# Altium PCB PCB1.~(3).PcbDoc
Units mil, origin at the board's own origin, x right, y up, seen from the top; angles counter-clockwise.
Board outline 6000 x 4000 mil, 2 copper layers (Top Layer, Bottom Layer); 19 components, 17 nets, 64 pads, 0 vias.
Unrouted connection lines stored in the file: 36.
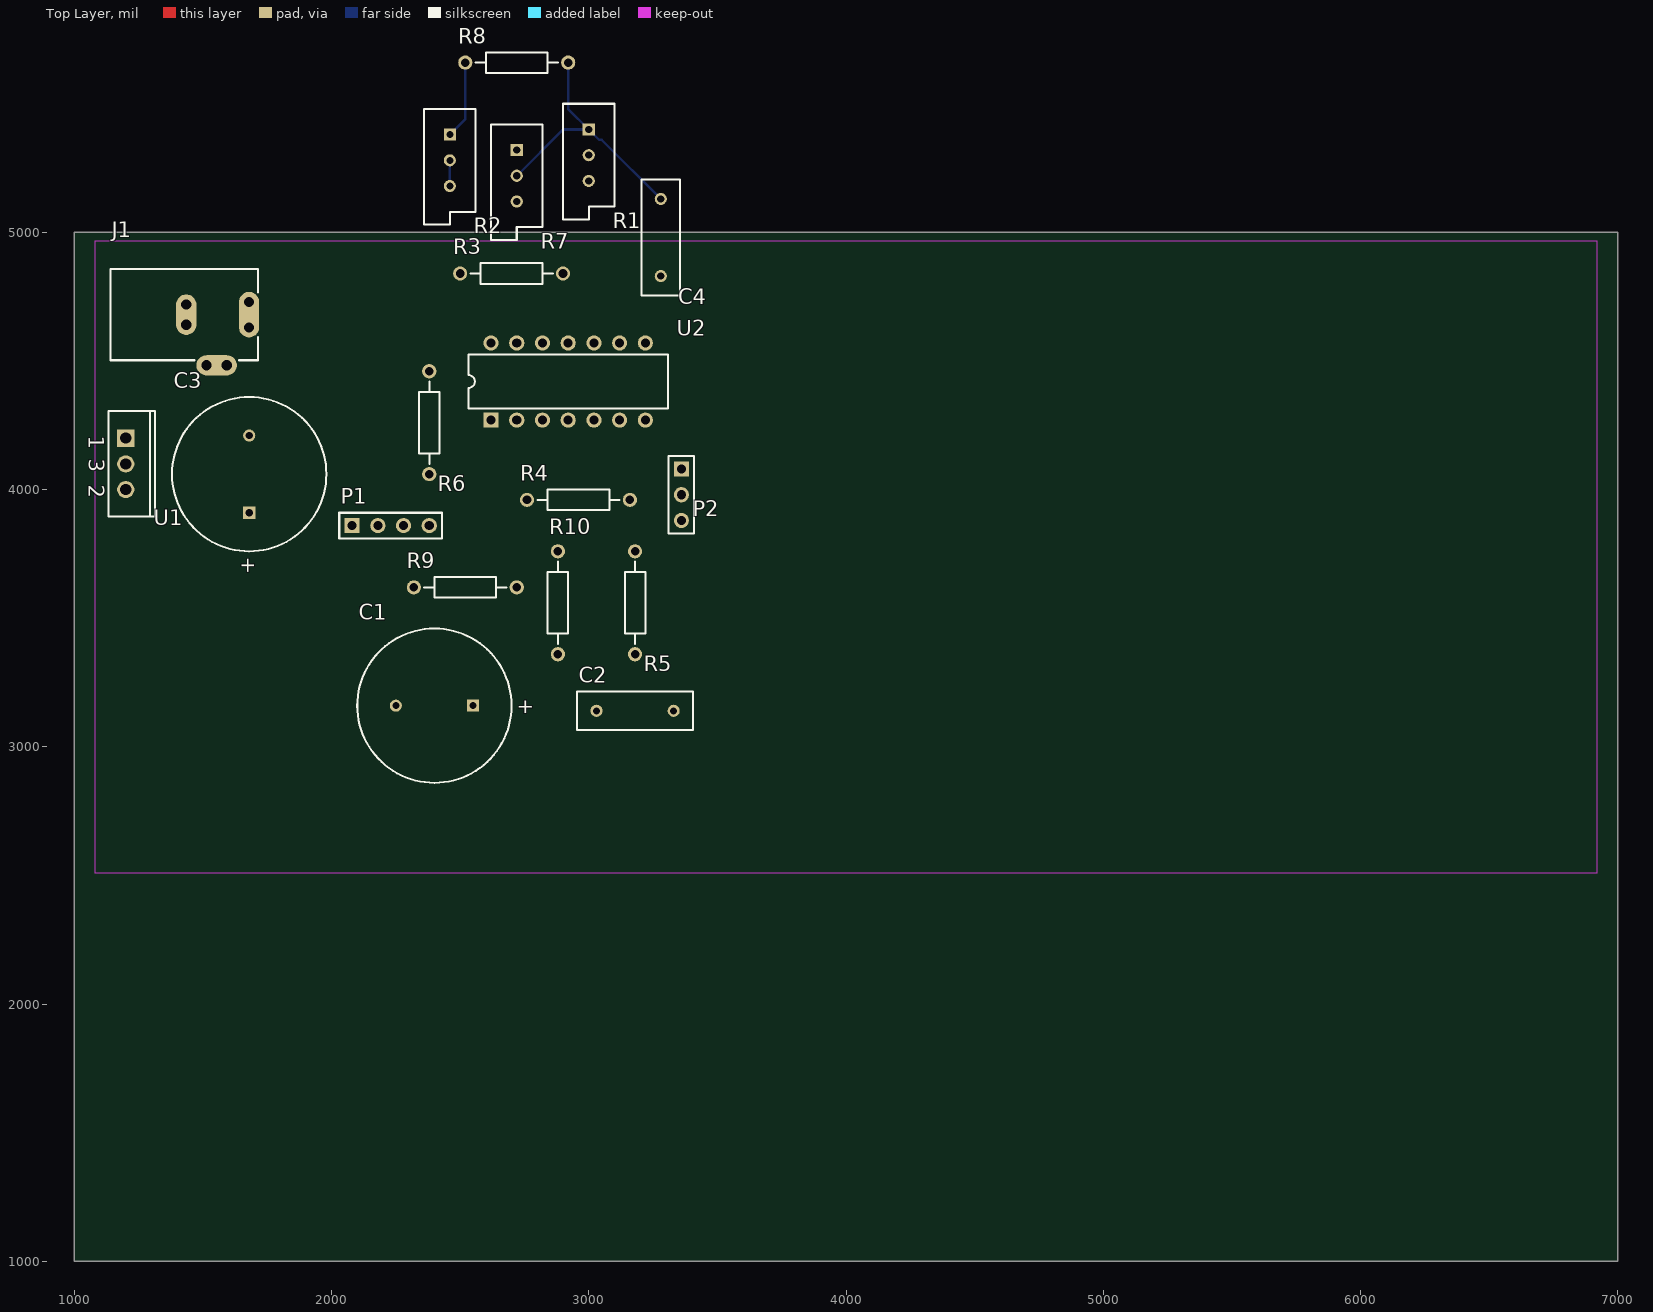
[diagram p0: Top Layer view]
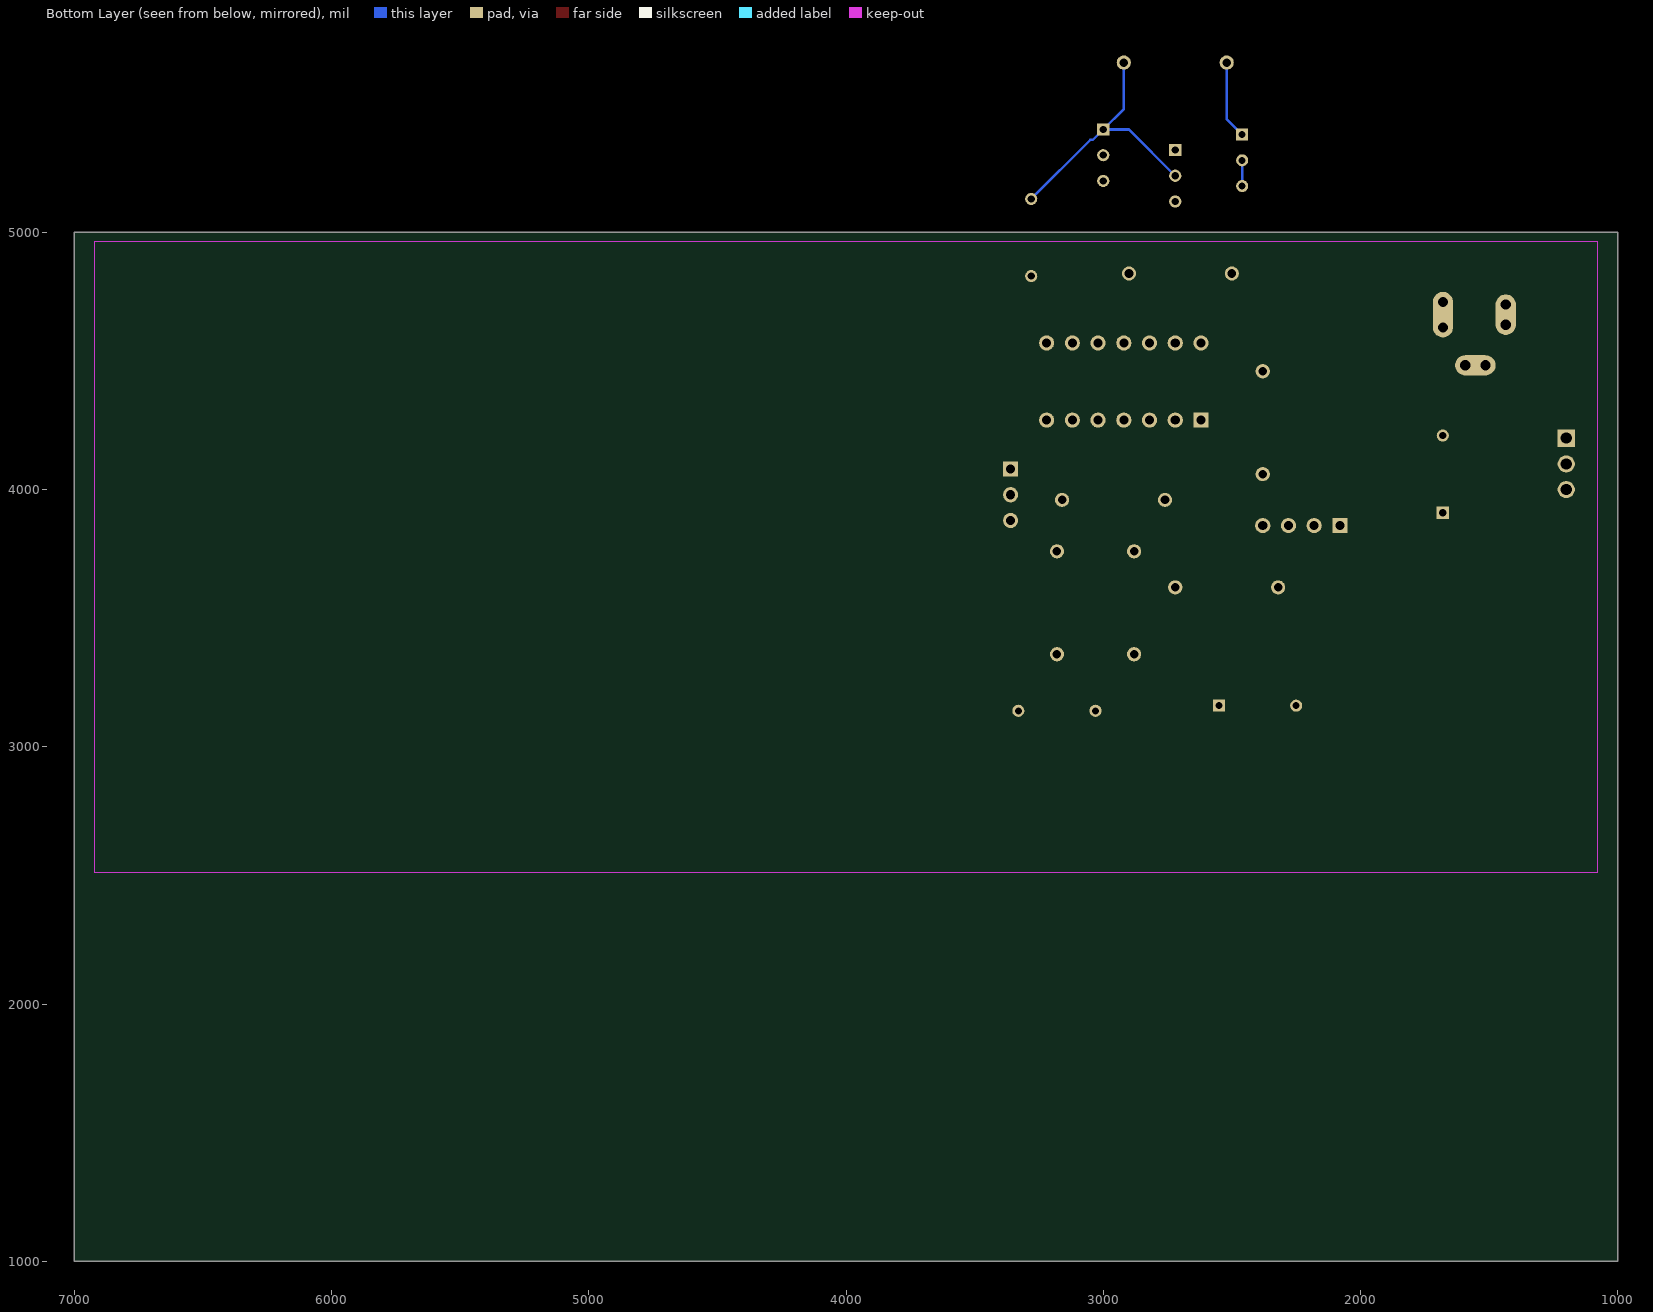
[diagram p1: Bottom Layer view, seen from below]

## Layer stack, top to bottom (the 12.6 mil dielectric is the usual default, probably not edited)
Top Layer: signal copper 1.4
Dielectric: dielectric 12.6, FR-4, Dk 4.8
Bottom Layer: signal copper 1.4

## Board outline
1000,1000 7000,1000 7000,5000 1000,5000

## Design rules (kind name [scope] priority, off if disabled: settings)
Clearance [All] p1: gap=10
ComponentClearance [All] p1: gap=10 collisioncheckmode=3 verticalgap=10
PolygonConnect [All] p1: connectstyle=Relief reliefconductorwidth=10 reliefentries=4 polygonreliefangle="90 Angle"
RoomDefinition Sheet1 [InComponentClass('Sheet1')] p1: confinementstyle=ConfineIn formatcopy=TRUE lockcomponents=FALSE outline 4185,2870 6800,2870 6800,3985 4185,3985
RoutingVias [All] p1: holewidth=28 width=50 viastyle="Through Hole" minholewidth=28 minwidth=50 maxholewidth=28 maxwidth=50
SolderMaskExpansion [All] p1: expansion=4
TestPointUsage [All] p1: valid=0 allowmultiple=FALSE
Testpoint [All] p1: side=15 testpointundercomponent=TRUE minsize=40 maxsize=100 preferedsize=60 minholesize=0 maxholesize=40 preferedholesize=32 testpointgrid=1 style=1023 order=0123456789
Width [All] p1: maxlimit=10 minlimit=10 preferedwidth=10
18 further rules are at their usual default settings.

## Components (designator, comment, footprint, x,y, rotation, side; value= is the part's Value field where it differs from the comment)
C1 "Cap Pol1" RB7.6-15 2400,3160 r0 top
C2 "Cap" RAD-0.3 3180,3140 r180 top
C3 "Cap Pol1" RB7.6-15 1680,4060 r270 top
C4 "Cap" RAD-0.3 3280,4980 r270 top
J1 "PWR2.5" KLD-0202 1140,4680 r0 top
P1 "Header 4" HDR1X4 2080,3860 r0 top
P2 "Header 3" HDR1X3 3360,4080 r270 top
R1 "RPot" VR5 3000,5300 r270 top
R2 "RPot" VR5 2460,5280 r270 top
R3 "Res2" AXIAL-0.4 2700,4840 r180 top
R4 "Res2" AXIAL-0.4 2960,3960 r0 top
R5 "Res2" AXIAL-0.4 3180,3560 r270 top
R6 "Res2" AXIAL-0.4 2380,4260 r270 top
R7 "RPot" VR5 2720,5220 r270 top
R8 "Res2" AXIAL-0.4 2720,5660 r0 top
R9 "Res2" AXIAL-0.4 2520,3620 r180 top
R10 "Res2" AXIAL-0.4 2880,3560 r90 top
U1 "L7812ABV" TO220ABN 1200,4100 r270 top
U2 "LM324AN" N14A 2920,4420 r0 top

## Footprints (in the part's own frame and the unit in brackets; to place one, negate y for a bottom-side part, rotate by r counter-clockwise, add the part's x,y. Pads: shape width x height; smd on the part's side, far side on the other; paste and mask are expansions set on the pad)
AXIAL-0.4 [mm] "Resistor; 2 Leads"
  round 1.4 hole 0.85: 1(-5.08,0) 2(5.08,0)
  silkscreen extent -4.06,-1.02 4.06,1.02
HDR1X3 [mm] "Connector; Header; 3 Position"
  rect 1.5x1.5 hole 0.9: 1(0,0)
  round 1.5 hole 0.9: 2(2.54,0) 3(5.08,0)
  silkscreen extent -1.27,-1.27 6.35,1.27
HDR1X4 [mm] "Connector; Header; 4 Position"
  rect 1.5x1.5 hole 0.9: 1(0,0)
  round 1.5 hole 0.9: 2(2.54,0) 3(5.08,0) 4(7.62,0)
  silkscreen extent -1.27,-1.27 8.89,1.27
KLD-0202 [mm] "DC Power Jack, 2.5mm, KLD Series, PCB Mount"
  oval 2x4.5 all layers, no hole: 1(13.7,0)
  round 1.5 hole 1: 1A(13.7,-1.25) 1B(13.7,1.25) 2A(7.5,-1) 2B(7.5,1) 3A(9.5,-5) 3B(11.5,-5)
  oval 2x4 all layers, no hole: 2(7.5,0)
  oval 4x2 all layers, no hole: 3(10.5,-5)
  silkscreen extent 0,-4.5 14.6,4.5
N14A [mm] "DIP; 14 Leads; Row Spacing 7.62 mm; Pitch 2.54 mm"
  rect 1.5x1.5 hole 0.9: 1(-7.62,-3.81)
  round 1.5 hole 0.9: 2(-5.08,-3.81) 3(-2.54,-3.81) 4(0,-3.81) 5(2.54,-3.81) 6(5.08,-3.81) 7(7.62,-3.81) 8(7.62,3.81) 9(5.08,3.81) 10(2.54,3.81) 11(0,3.81) 12(-2.54,3.81) 13(-5.08,3.81) 14(-7.62,3.81)
  silkscreen extent -9.85,-2.65 9.85,2.65
RAD-0.3 [mm] "Capacitor; 2 Leads"
  round 1.2 hole 0.7: 1(-3.81,0) 2(3.81,0)
  silkscreen extent -5.71,-1.91 5.71,1.91
RB7.6-15 [mm] "Polarized Capacitor (Radial); 2 Leads"
  rect 1.2x1.2 hole 0.7: 1(3.81,0)
  round 1.2 hole 0.7: 2(-3.81,0)
  silkscreen extent -7.62,-7.62 7.62,7.62
TO220ABN [mm] "TO, Thru-Hole, Vertical, Heatsink Mounted; 3 In-Line Leads; Pitch 2.54 mm; Pin sequence 1, 3, 2"
  rect 1.7x1.7 hole 1.1: 1(-2.54,0)
  round 1.7 hole 1.1: 2(2.54,0) 3(0,0)
  silkscreen extent -5.2,-1.7 5.2,2.9
VR5 [mm] "Potentiometer; 3 Leads"
  rect 1.2x1.2 hole 0.7: 1(-2.54,0)
  round 1.2 hole 0.7: 2(0,0) 3(2.54,0)
  silkscreen extent -5.08,-2.54 6.35,2.54

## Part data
C1 C3: "Polarized Capacitor (Radial)"
C2 C4: "Capacitor"
J1: "Low Voltage Power Supply Connector"
P1: "Header, 4-Pin"
P2: library part "Header 2", "Header, 2-Pin"
R1 R2 R7: "Potentiometer"
R3 R4 R5 R6 R8 R9 R10: "Resistor"
U1: "Precision 1A Regulator"
U2: "Low-Power Quad Operational Amplifier"

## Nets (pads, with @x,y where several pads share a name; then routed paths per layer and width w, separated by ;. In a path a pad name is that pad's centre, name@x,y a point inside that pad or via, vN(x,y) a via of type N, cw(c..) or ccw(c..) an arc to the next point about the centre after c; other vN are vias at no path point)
+5: C1.2 P1.1 P2.1 R1.2 U1.2 U2.4
GND: C1.1 C3.2 C4.1 J1.1 J1.1A J1.1B P1.4 P2.3 R1.1 R7.2 R8.2 R9.1 R10.2 U1.3 U2.11 | length 1039.5
  Bottom Layer w10: R7.2 2900,5400 R1.1 ; R8.2 2920,5480 R1.1 ; C4.1 3050,5360 3040,5360 R1.1
NetC2_1: C2.1 R10.1 U2.5
NetC2_2: C2.2 R5.1
NetC3_1: C3.1 R4.1 U2.3
NetC4_2: C4.2 R6.1 U2.12
NetJ1_3: J1.3 J1.3A J1.3B
NetP1_2: P1.2 R6.2 R9.2
NetP1_3: P1.3 R1.3
NetP2_2: P2.2 R7.1 U2.8
NetR2_1: R2.1 R8.1 U2.2 | length 304.9
  Bottom Layer w10: R2.1 2520,5440 R8.1
NetR2_2: R2.2 R2.3 R3.2 U2.1 | length 100
  Bottom Layer w10: R2.3 R2.2
NetR3_1: R3.1 U2.9
NetR4_2: R4.2 U2.6 U2.7
NetR5_2: R5.2 U2.13 U2.14
NetR7_3: R7.3 U2.10
VCC: J1.2 J1.2A J1.2B U1.1

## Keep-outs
Keep-Out Layer:
  rectangle: 1080,2510 6920,4965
